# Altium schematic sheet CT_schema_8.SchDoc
size 287 x 160 mm
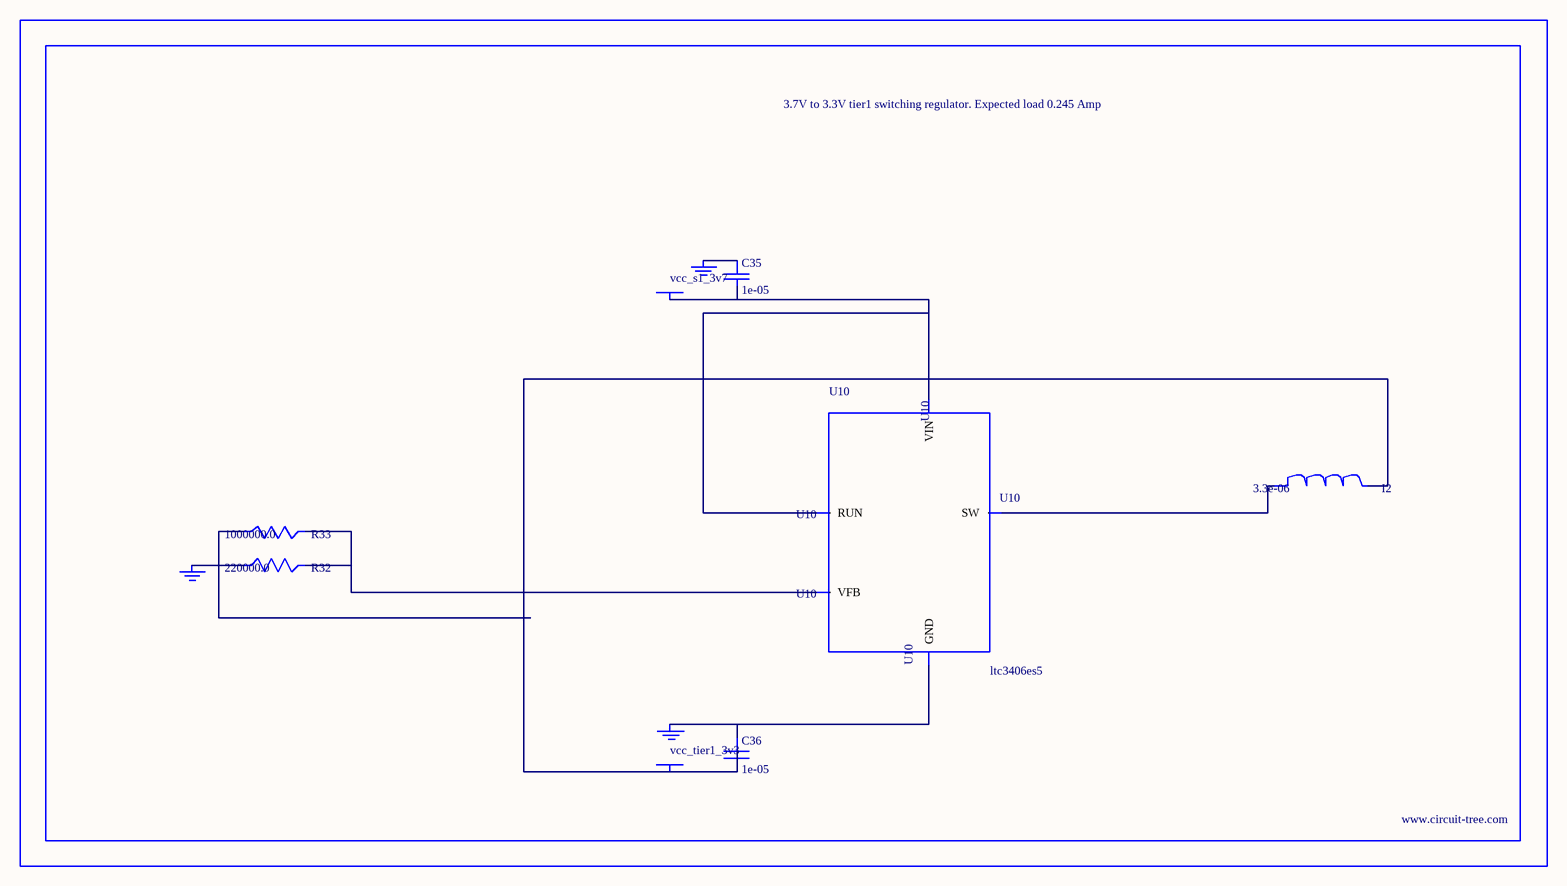
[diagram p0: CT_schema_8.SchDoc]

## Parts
BORDER7  (no value)
C35  1e-05  [C0805]
C36  1e-05  [C0805]
GND_INSTANCE_7_0  (no value)
GND_INSTANCE_7_1  (no value)
GND_INSTANCE_7_2  (no value)
I2  3.3e-06  [L0806]
POWER_INSTANCE_7_0  vcc_tier1_3v3
POWER_INSTANCE_7_1  vcc_s1_3v7
R32  220000.0  [R0603]
R33  1000000.0  [R0603]
U10  ltc3406es5  [TSOT-23-5]

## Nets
NetC35_1: C35.1 GND_INSTANCE_7_1.0(GND)
NetC35_2: C35.2 POWER_INSTANCE_7_1.0(PWR) U10.1(RUN) U10.4(VIN)
NetC36_1: C36.1 GND_INSTANCE_7_0.0(GND) U10.2(GND)
NetC36_2: C36.2 I2.2 POWER_INSTANCE_7_0.0(PWR) R33.1
NetGND_INSTANCE_7_2_0: GND_INSTANCE_7_2.0(GND) R32.1
NetI2_1: I2.1 U10.3(SW)
NetR32_2: R32.2 R33.2 U10.5(VFB)

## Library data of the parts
BORDER7 = BORDER_PAGE7
C35 C36 = C0805C106K8RACTU
GND_INSTANCE_7_0-GND_INSTANCE_7_2 = GND
I2 = L0806C3R3MDWIT
POWER_INSTANCE_7_0 POWER_INSTANCE_7_1 = PWR
R32 = RC0603JR-07220KL
R33 = RC0603JR-071ML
